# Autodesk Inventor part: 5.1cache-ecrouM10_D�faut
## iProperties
Created: 2011-01
Part Number: 5.1cache-ecrouM10_D�faut
Document SubType Name: Modeling
Designer: eric
Density: 1 g/cm^3
Mass: 2.7477 g
Surface Area: 26.0068 cm^2
Volume: 2.7477 cm^3
Author: eric
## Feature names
1. Base1
